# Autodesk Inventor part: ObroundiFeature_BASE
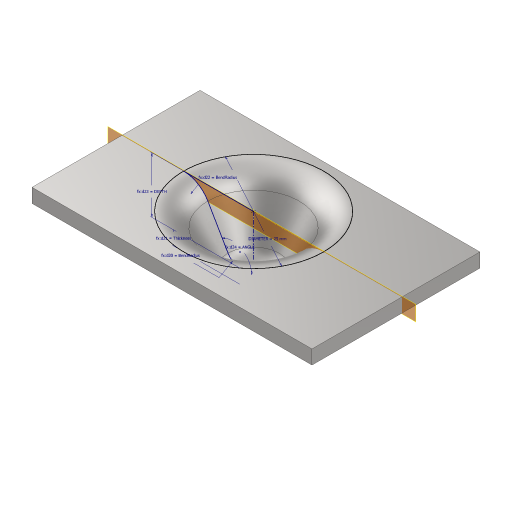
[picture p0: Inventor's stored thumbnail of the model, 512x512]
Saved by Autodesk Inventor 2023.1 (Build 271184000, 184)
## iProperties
Category: Autodesk® Inventor® Tutorial Series
Company: Fabian Stasiak CAD Consulting
Created: 2022-08
Part Number: ObroundiFeature_BASE
Material: Steel
Document SubType Name: Sheet Metal
Designer: F.Stasiak
Density: 7.85 g/cm^3
Sheet Metal Rule: Steel 2.5 mm/Round
Appearance: Stainless - Brushed
Catalog Web Link: www.expertbooks.eu
Thickness: 2,5
FLATAREA: =<FLAT PATTERN AREA>
Author: F.Stasiak
Subject: Sheet Metal Design. Basic and Advanced techniques
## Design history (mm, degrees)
node "Face1"
  sketch "Sketch1"
    geometry: L1 (25, -15)-(-25, -15); L2 (-25, -15)-(-25, 15); L3 (-25, 15)-(25, 15); L4 (25, 15)-(25, -15); L5 (25, -15)-(-25, 15); L6 (-25, -15)-(25, 15); 1 further point
    constraints: 12 end point, 2 midpoint, 2 parallel, 1 horizontal, 1 perpendicular
    dimensions: "d0" = 50 distance of L2.end L3.end; "d1" = 30 distance of L1.end L2.end
sketch "Sketch2"
  geometry: L1 (-14.007, 1.058)-(10.993, 1.058); A1 r 12.5 centre (-1.507, 1.058) between (-14.007, 1.058) and (10.993, 1.058); 2 further points
  constraints: 2 coincident, 2 end point, 2 point on circle, 1 centre point, 1 horizontal, 1 midpoint
  dimensions: "DIAMETER" = 25 diameter of A1
workplane "Work Plane5"
sketch "Sketch5"
  geometry: L1 (25, 0)-(0, 0) reference; L2 (4.33, -2.5)-(7.939, -8.75); L3 (10.104, -10)-(12.5, -10); L4 (2.165, -3.75)-(5.774, -10); L5 (10.104, -12.5)-(12.5, -12.5); L6 (0, -2.5)-(0, 0); L7 (0, 0)-(12.5, 0); L8 (12.5, 0)-(12.5, -12.5); A1 r 5 centre (0, -5) between (4.33, -2.5) and (0, 0); A2 r 2.5 centre (10.104, -7.5) between (7.939, -8.75) and (10.104, -10); A3 r 2.5 centre (0, -5) between (2.165, -3.75) and (0, -2.5); A4 r 5 centre (10.104, -7.5) between (5.774, -10) and (10.104, -12.5); 1 further point
  constraints: 14 end point, 8 point on circle, 4 centre point, 4 tangent, 2 vertical alignment, 1 collinear, 1 horizontal, 1 perpendicular, 3 other
  dimensions: "d20" = 2.5 radius of A2 (= BendRadius); "d21" = 2.5 distance between parallel lines of L5 L3 (= Thickness); "d22" = 2.5 radius of A3 (= BendRadius); "d23" = 10 distance between parallel lines of L1 L3 (= DEPTH); "d24" = 120 deg angle of L3 L2 (= ANGLE)
revolve "Revolution5" stored, may be unused: angle "d25" = 90 deg
revolve "Revolution6" stored, may be unused: angle "d26" = 90 deg
body "Solid1"
face "Plate1" dims "d2" = 2.5 (= Thickness)
other parameters: "Thickness" = 2.5 (derived), "BendRadius" = 2.5 (= Thickness), "BendReliefWidth" = 2.5 (= Thickness), "BendReliefDepth" = 1.25 (= 0.5 x Thickness), "SeamGap" = 0.01, "MinimumRemnant" = 5 (= 2 x Thickness), "TransitionRadius" = 2.5 (= BendRadius), "JacobiRadiusSize" = 2.5 (= BendRadius), "GapSize" = 2.5 (= Thickness), "DEPTH" = 10 [user parameter; used in 1 equation term], "ANGLE" = 120 deg [user parameter; used in 1 equation term], "d19" = 90 deg
